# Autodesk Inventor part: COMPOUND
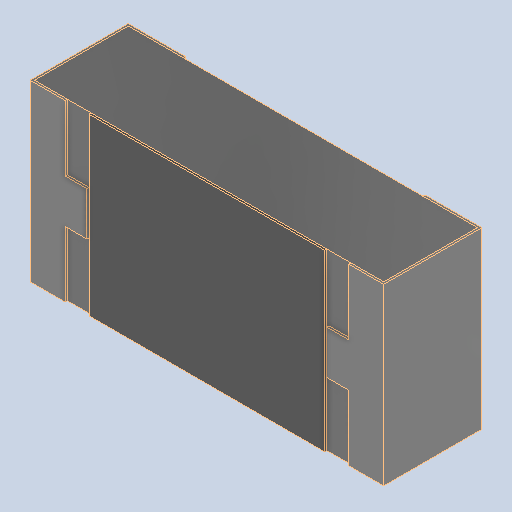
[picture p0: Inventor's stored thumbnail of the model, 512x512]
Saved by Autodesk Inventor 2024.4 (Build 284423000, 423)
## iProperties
Created: 2025-05
Part Number: COMPOUND
Material: Generic
Document SubType Name: Modeling
Designer: AdminForWorker
Density: 1 g/cm^3
Appearance: Default
Title: COMPOUND (2)
Author: AdminForWorker
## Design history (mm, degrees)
feature "Body1"
feature "Body2"
feature "Body3"
feature "Body4"
body "Solid1"
body "Solid2"
body "Solid3"
body "Solid4"
